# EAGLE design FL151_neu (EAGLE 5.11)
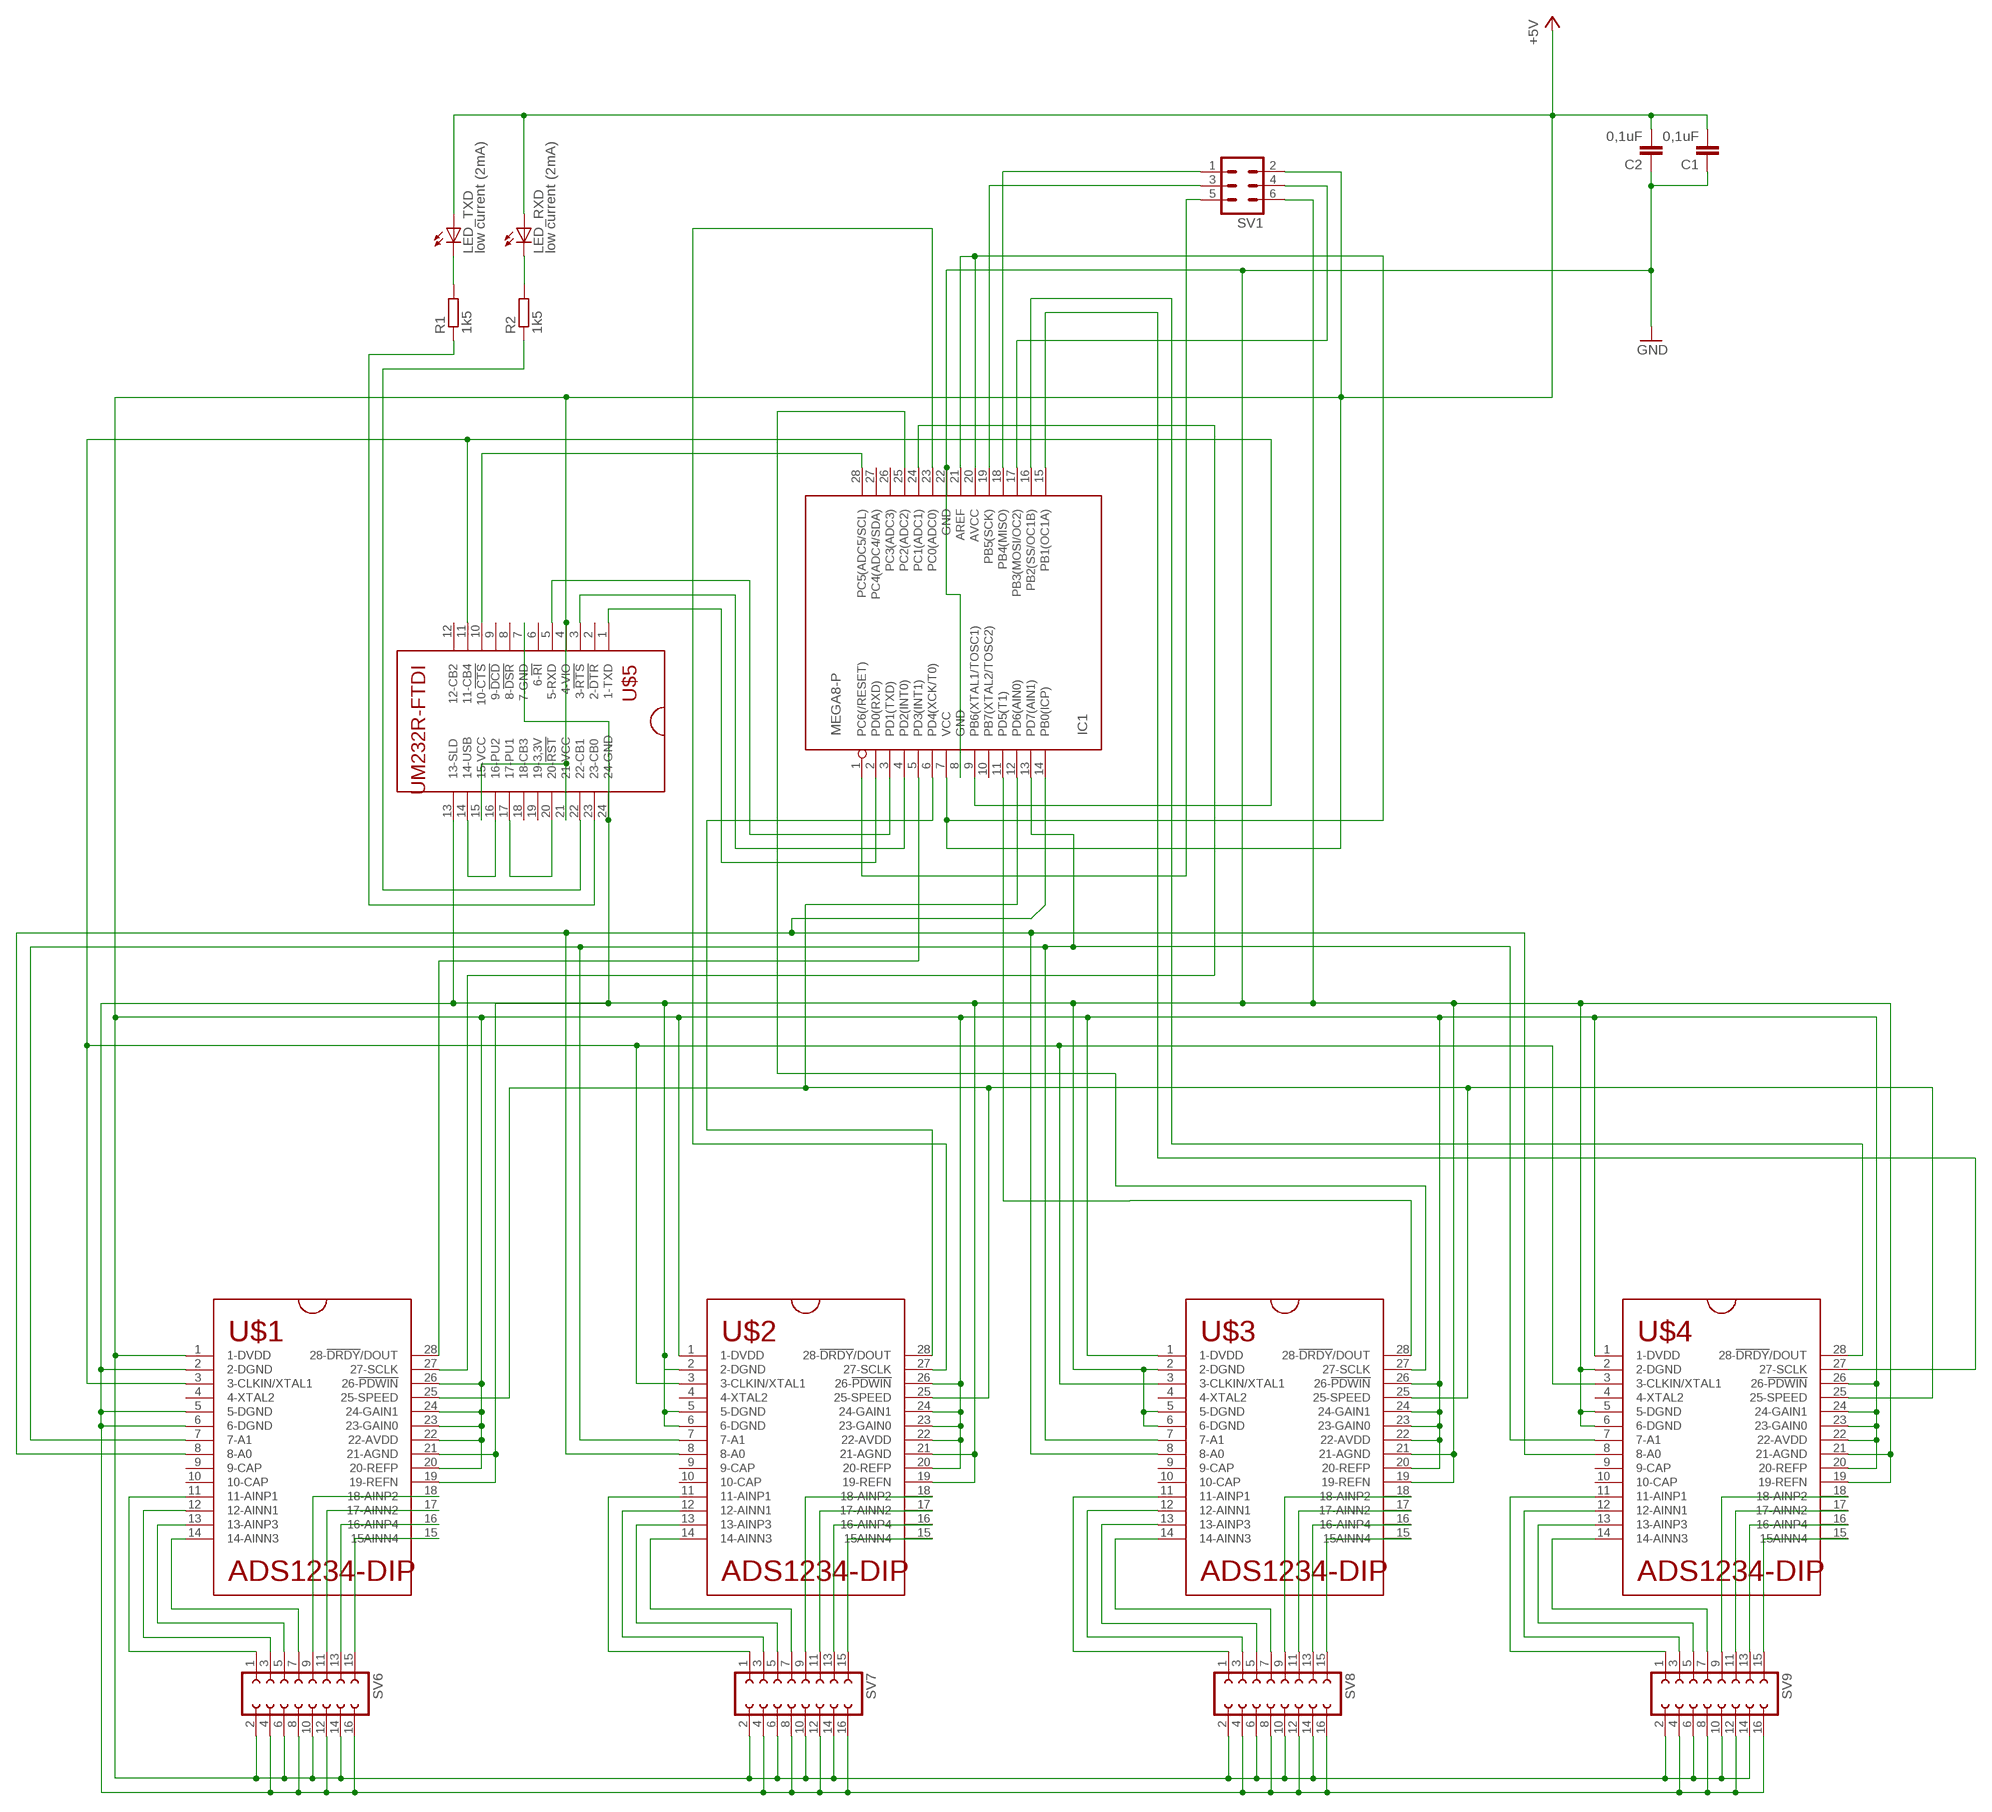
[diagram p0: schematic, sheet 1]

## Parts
C1  0,1uF  C-EU025-025X050  [C025-025X050]
C2  0,1uF  C-EU025-025X050  [C025-025X050]
IC1  MEGA8-P  [DIL28-3]
LED_RXD  low current (2mA)  LED3MM  [LED3MM]
LED_TXD  low current (2mA)  LED3MM  [LED3MM]
R1  1k5  R-EU_0207/10  [0207/10]
R2  1k5  R-EU_0207/10  [0207/10]
SV1  ML6  [ML6]
SV6  FE08-2  [FE08-2]
SV7  FE08-2  [FE08-2]
SV8  FE08-2  [FE08-2]
SV9  FE08-2  [FE08-2]
U$1  ADS1234-DIP  [ADS1234-DIP]
U$2  ADS1234-DIP  [ADS1234-DIP]
U$3  ADS1234-DIP  [ADS1234-DIP]
U$4  ADS1234-DIP  [ADS1234-DIP]
U$5  UM232R-FTDI  [UM232R-FTDI]

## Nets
+5V: C1.2 C2.2 IC1.7(VCC) IC1.20(AVCC) IC1.21(AREF) LED_RXD.A LED_TXD.A SV1.2 SV6.2 SV6.6 SV6.10 SV6.14 SV7.2 SV7.6 SV7.10 SV7.14 SV8.2 SV8.6 SV8.10 SV8.14 SV9.2 SV9.6 SV9.10 SV9.14 U$1.1(1-DVDD) U$1.20(20-REFP) U$1.22(22-AVDD) U$1.23(23-GAIN0) U$1.24(24-GAIN1) U$1.26(26-!PDWIN) U$2.1(1-DVDD) U$2.20(20-REFP) U$2.22(22-AVDD) U$2.23(23-GAIN0) U$2.24(24-GAIN1) U$2.26(26-!PDWIN) U$3.1(1-DVDD) U$3.20(20-REFP) U$3.22(22-AVDD) U$3.23(23-GAIN0) U$3.24(24-GAIN1) U$3.26(26-!PDWIN) U$4.1(1-DVDD) U$4.20(20-REFP) U$4.22(22-AVDD) U$4.23(23-GAIN0) U$4.24(24-GAIN1) U$4.26(26-!PDWIN) U$5.4(4-VIO) U$5.15(15-VCC) U$5.21(21-VCC)
GND: C1.1 C2.1 IC1.8(GND) IC1.22(GND) SV1.6 SV6.4 SV6.8 SV6.12 SV6.16 SV7.4 SV7.8 SV7.12 SV7.16 SV8.4 SV8.8 SV8.12 SV8.16 SV9.4 SV9.8 SV9.12 SV9.16 U$1.2(2-DGND) U$1.5(5-DGND) U$1.6(6-DGND) U$1.19(19-REFN) U$1.21(21-AGND) U$2.2(2-DGND) U$2.5(5-DGND) U$2.6(6-DGND) U$2.19(19-REFN) U$2.21(21-AGND) U$3.2(2-DGND) U$3.5(5-DGND) U$3.6(6-DGND) U$3.19(19-REFN) U$3.21(21-AGND) U$4.2(2-DGND) U$4.5(5-DGND) U$4.6(6-DGND) U$4.19(19-REFN) U$4.21(21-AGND) U$5.7(7-GND) U$5.13(13-SLD) U$5.24(24-GND)
ISP: IC1.1(PC6(/RESET)) SV1.5
N$1: LED_TXD.K(C) R1.2
N$2: LED_RXD.K(C) R2.2
N$3: IC1.2(PD0(RXD)) U$5.1(1-TXD)
N$4: IC1.4(PD2(INT0)) U$5.3(3-!RTS)
N$5: IC1.3(PD1(TXD)) U$5.5(5-RXD)
N$6: IC1.6(PD4(XCK/T0)) U$2.28(28-!DRDY!/DOUT)
N$7: U$5.14(14-USB) U$5.16(16-PU2)
N$8: U$5.17(17-PU1) U$5.20(20-!RST)
N$9: IC1.24(PC1(ADC1)) U$1.27(27-SCLK)
N$10: R2.1 U$5.22(22-CB1)
N$11: R1.1 U$5.23(23-CB0)
N$12: SV6.1 U$1.11(11-AINP1)
N$13: IC1.5(PD3(INT1)) U$1.28(28-!DRDY!/DOUT)
N$14: IC1.15(PB1(OC1A)) U$4.27(27-SCLK)
N$15: IC1.16(PB2(SS/OC1B)) U$4.28(28-!DRDY!/DOUT)
N$16: IC1.12(PD6(AIN0)) U$1.25(25-SPEED) U$2.25(25-SPEED) U$3.25(25-SPEED) U$4.25(25-SPEED)
N$17: IC1.13(PD7(AIN1)) U$1.7(7-A1) U$2.7(7-A1) U$3.7(7-A1) U$4.7(7-A1)
N$18: IC1.25(PC2(ADC2)) U$3.27(27-SCLK)
N$19: IC1.11(PD5(T1)) U$3.28(28-!DRDY!/DOUT)
N$20: IC1.23(PC0(ADC0)) U$2.27(27-SCLK)
N$22: IC1.14(PB0(ICP)) U$1.8(8-A0) U$2.8(8-A0) U$3.8(8-A0) U$4.8(8-A0)
N$23: IC1.9(PB6(XTAL1/TOSC1)) U$1.3(3-CLKIN/XTAL1) U$2.3(3-CLKIN/XTAL1) U$3.3(3-CLKIN/XTAL1) U$4.3(3-CLKIN/XTAL1) U$5.11(11-CB4)
N$24: SV6.3 U$1.12(12-AINN1)
N$25: SV6.5 U$1.13(13-AINP3)
N$26: SV6.7 U$1.14(14-AINN3)
N$27: SV6.9 U$1.18(18-AINP2)
N$28: SV6.11 U$1.17(17-AINN2)
N$29: SV6.13 U$1.16(16-AINP4)
N$30: SV6.15 U$1.15(15AINN4)
N$31: SV7.1 U$2.11(11-AINP1)
N$32: SV7.3 U$2.12(12-AINN1)
N$33: SV7.5 U$2.13(13-AINP3)
N$34: SV7.7 U$2.14(14-AINN3)
N$35: SV7.9 U$2.18(18-AINP2)
N$36: SV7.11 U$2.17(17-AINN2)
N$37: SV7.13 U$2.16(16-AINP4)
N$38: SV7.15 U$2.15(15AINN4)
N$39: SV8.1 U$3.11(11-AINP1)
N$40: SV8.3 U$3.12(12-AINN1)
N$41: SV8.5 U$3.13(13-AINP3)
N$42: SV8.7 U$3.14(14-AINN3)
N$43: SV8.9 U$3.18(18-AINP2)
N$44: SV8.11 U$3.17(17-AINN2)
N$45: SV8.13 U$3.16(16-AINP4)
N$46: SV8.15 U$3.15(15AINN4)
N$47: SV9.1 U$4.11(11-AINP1)
N$48: SV9.3 U$4.12(12-AINN1)
N$49: SV9.5 U$4.13(13-AINP3)
N$50: SV9.7 U$4.14(14-AINN3)
N$51: SV9.9 U$4.18(18-AINP2)
N$52: SV9.11 U$4.17(17-AINN2)
N$53: SV9.13 U$4.16(16-AINP4)
N$54: SV9.15 U$4.15(15AINN4)
N$55: IC1.19(PB5(SCK)) SV1.3
N$56: IC1.17(PB3(MOSI/OC2)) SV1.4
N$57: IC1.18(PB4(MISO)) SV1.1
N$58: IC1.28(PC5(ADC5/SCL)) U$5.10(10-!CTS)
Unconnected: IC1.10(PB7(XTAL2/TOSC2)) IC1.26(PC3(ADC3)) IC1.27(PC4(ADC4/SDA)) U$1.4(4-XTAL2) U$1.9(9-CAP) U$1.10(10-CAP) U$2.4(4-XTAL2) U$2.9(9-CAP) U$2.10(10-CAP) U$3.4(4-XTAL2) U$3.9(9-CAP) U$3.10(10-CAP) U$4.4(4-XTAL2) U$4.9(9-CAP) U$4.10(10-CAP) U$5.2(2-!DTR) U$5.6(6-!RI) U$5.8(8-!DSR) U$5.9(9-!DCD) U$5.12(12-CB2) U$5.18(18-CB3) U$5.19(19-3,3V)

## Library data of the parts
C1 C2 = rcl:C-EU: CAPACITOR, European symbol
IC1 = balzes_bauteile:MEGA8-P: MICROCONTROLLER 8 Kbytes FLASH, 1 kbytes SRAM, 512 bytes EEPROM, USART, 4-channel 10 bit ADC, 2-channel 8 bit ADC Pin compatible with Atmega48, ATMega88, ATMega168 Source: avr.lbr
LED_RXD LED_TXD = led:LED: LED
R1 R2 = rcl:R-EU_: RESISTOR, European symbol
SV1 = con-harting-ml:ML6: HARTING
SV6-SV9 = con-lsta:FE08-2: FEMALE HEADER
U$1-U$4 = balzes_bauteile:ADS1234-DIP: Texas Instruments ADS1234 auf break-out-board DIP28,6 4 Kanal 24-bit Analog-Digital-Converter für Messbrücken
U$5 = balzes_bauteile:UM232R-FTDI

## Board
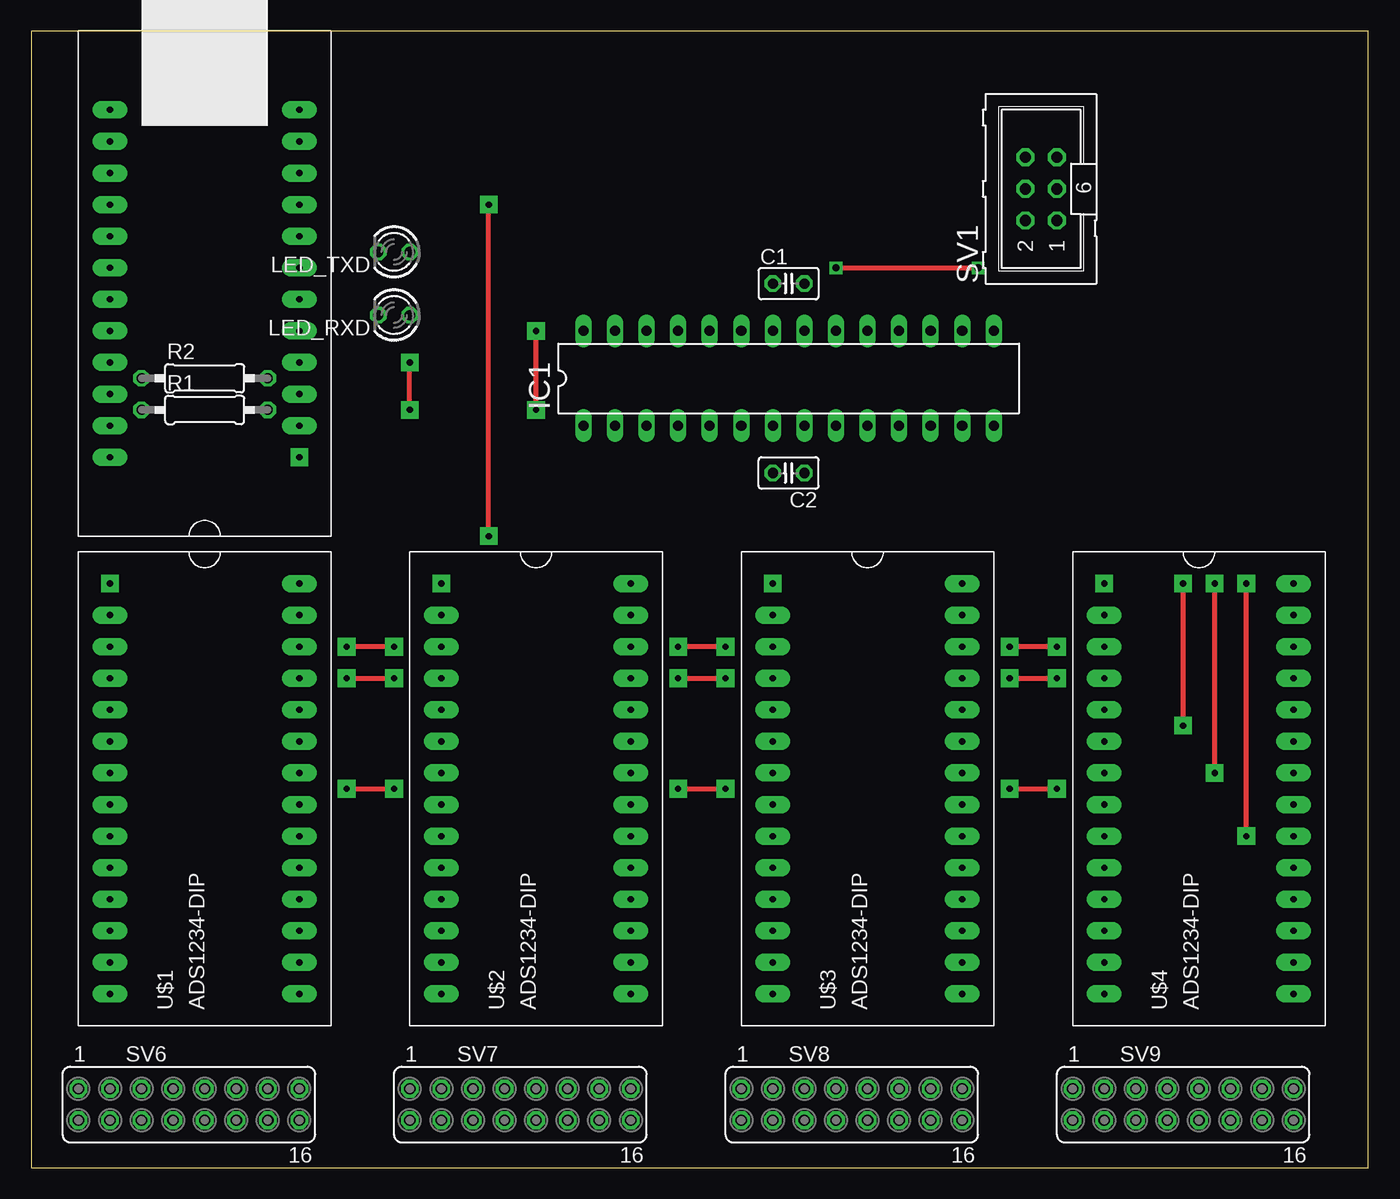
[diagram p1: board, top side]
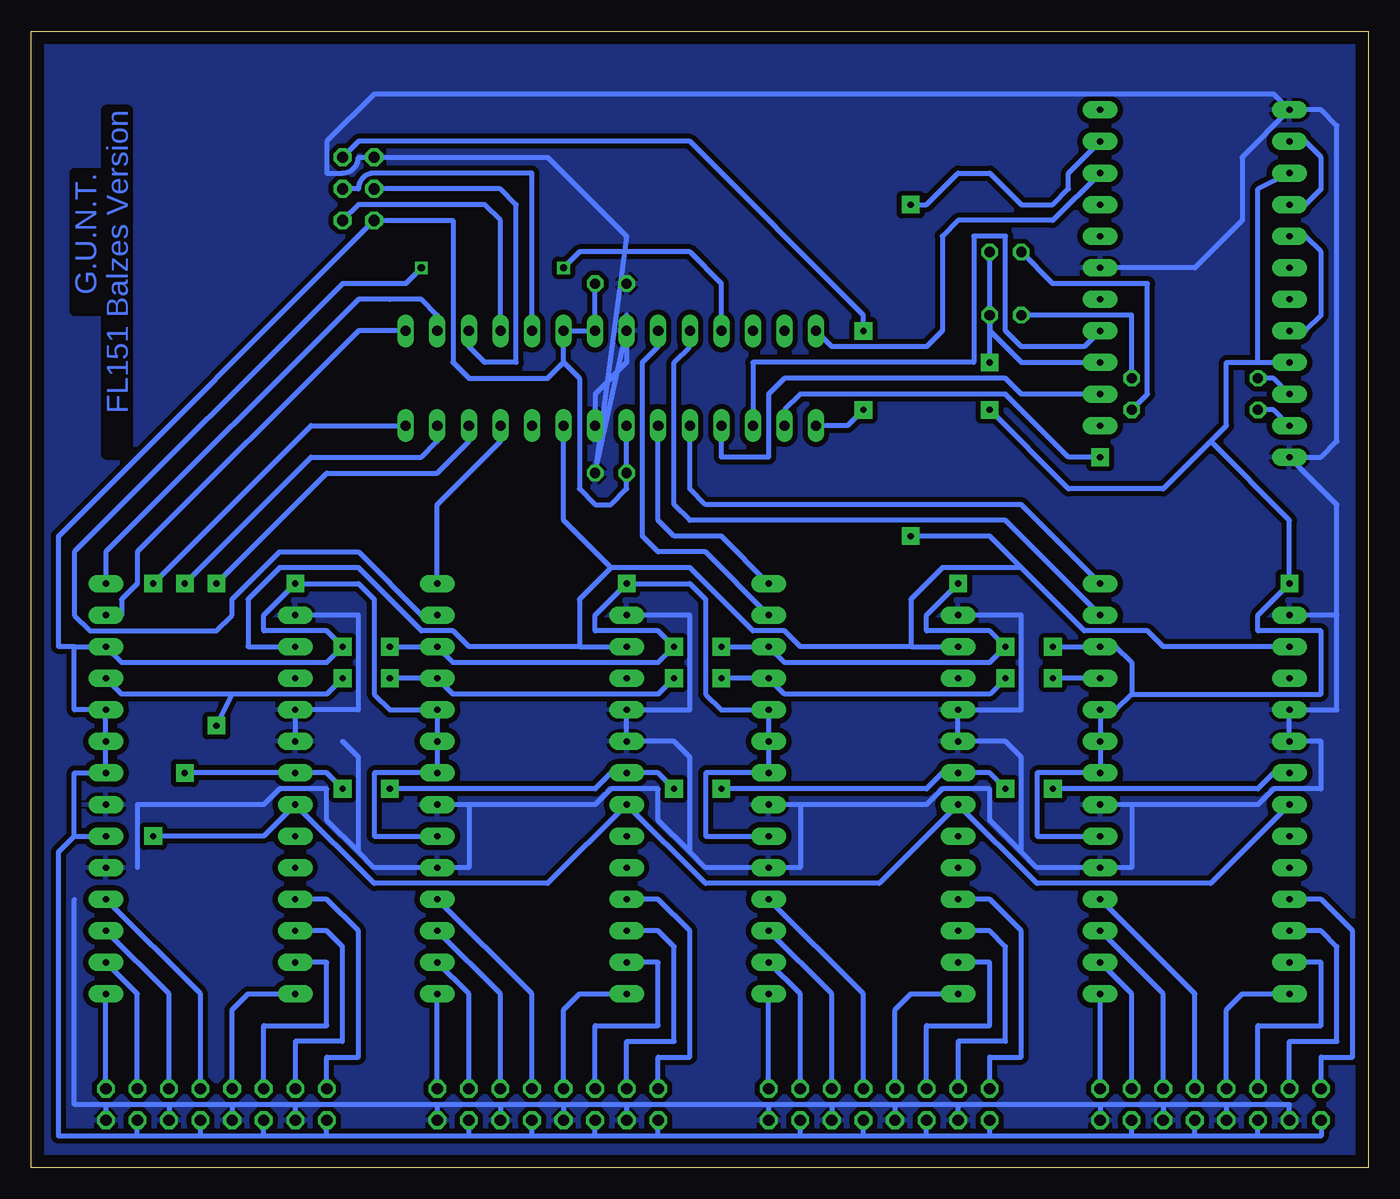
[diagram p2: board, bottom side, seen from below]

Size 107.62 x 91.43 mm. Coordinates in mm from the lower left corner, seen from the top.
Outline: 0,0 107.62,0 107.62,91.43 0,91.43 0,0
Copper layers (1*16): Top 0.035mm / dielectric 1.5mm / Bottom 0.035mm
Design rules "default": minimum track width 10mil, minimum drill 24mil, track to track 8mil, track to pad 8mil, pad to pad 8mil, via to via 8mil, smd to smd 8mil, copper to edge 40mil, drill to drill 8mil, minimum pad ring 10mil, minimum via ring 8mil, stop-mask expansion 4mil, vias tented up to drill 0mil, thermal gap 10mil

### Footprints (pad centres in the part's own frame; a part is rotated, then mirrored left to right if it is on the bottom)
C025-025X050 = drill 0.813 octagon: 1 -1.27,0; 2 1.27,0
DIL28-3 = drill 0.813 long: 1 -16.51,-3.81; 2 -13.97,-3.81; 3 -11.43,-3.81; 4 -8.89,-3.81; 5 -6.35,-3.81; 6 -3.81,-3.81; 7 -1.27,-3.81; 8 1.27,-3.81; 9 3.81,-3.81; 10 6.35,-3.81; 11 8.89,-3.81; 12 11.43,-3.81; 13 13.97,-3.81; 14 16.51,-3.81; 15 16.51,3.81; 16 13.97,3.81; 17 11.43,3.81; 18 8.89,3.81; 19 6.35,3.81; 20 3.81,3.81; 21 1.27,3.81; 22 -1.27,3.81; 23 -3.81,3.81; 24 -6.35,3.81; 25 -8.89,3.81; 26 -11.43,3.81; 27 -13.97,3.81; 28 -16.51,3.81
LED3MM = drill 0.813 octagon: A -1.27,0; K 1.27,0
0207/10 = drill 0.813 octagon: 1 -5.08,0; 2 5.08,0
ML6 = drill 0.914 octagon: 1 -2.54,-1.27; 2 -2.54,1.27; 3 0,-1.27; 4 0,1.27; 5 2.54,-1.27; 6 2.54,1.27
FE08-2 = drill 0.914 octagon: 1 -8.89,1.27; 2 -8.89,-1.27; 3 -6.35,1.27; 4 -6.35,-1.27; 5 -3.81,1.27; 6 -3.81,-1.27; 7 -1.27,1.27; 8 -1.27,-1.27; 9 1.27,1.27; 10 1.27,-1.27; 11 3.81,1.27; 12 3.81,-1.27; 13 6.35,1.27; 14 6.35,-1.27; 15 8.89,1.27; 16 8.89,-1.27
ADS1234-DIP = drill 0.5 pad 1.422 square: 1 -7.62,16.51 | drill 0.5 pad 1.422 long: 2 -7.62,13.97; 3 -7.62,11.43; 4 -7.62,8.89; 5 -7.62,6.35; 6 -7.62,3.81; 7 -7.62,1.27; 8 -7.62,-1.27; 9 -7.62,-3.81; 10 -7.62,-6.35; 11 -7.62,-8.89; 12 -7.62,-11.43; 13 -7.62,-13.97; 14 -7.62,-16.51; 15 7.62,-16.51; 16 7.62,-13.97; 17 7.62,-11.43; 18 7.62,-8.89; 19 7.62,-6.35; 20 7.62,-3.81; 21 7.62,-1.27; 22 7.62,1.27; 23 7.62,3.81; 24 7.62,6.35; 25 7.62,8.89; 26 7.62,11.43; 27 7.62,13.97; 28 7.62,16.51
UM232R-FTDI = drill 0.5 pad 1.422 square: 1 -16.51,30.48 | drill 0.5 pad 1.422 long: 2 -16.51,27.94; 3 -16.51,25.4; 4 -16.51,22.86; 5 -16.51,20.32; 6 -16.51,17.78; 7 -16.51,15.24; 8 -16.51,12.7; 9 -16.51,10.16; 10 -16.51,7.62; 11 -16.51,5.08; 12 -16.51,2.54; 13 -1.27,2.54; 14 -1.27,5.08; 15 -1.27,7.62; 16 -1.27,10.16; 17 -1.27,12.7; 18 -1.27,15.24; 19 -1.27,17.78; 20 -1.27,20.32; 21 -1.27,22.86; 22 -1.27,25.4; 23 -1.27,27.94; 24 -1.27,30.48

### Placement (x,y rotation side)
C1  60.96,71.12 0 top
C2  60.96,55.88 180 top
IC1  60.96,63.5 0 top
LED_RXD  29.21,68.58 180 top
LED_TXD  29.21,73.66 180 top
R1  13.97,60.96 0 top
R2  13.97,63.5 0 top
SV1  81.28,78.74 90 top
SV6  12.7,5.08 0 top
SV7  39.37,5.08 0 top
SV8  66.04,5.08 0 top
SV9  92.71,5.08 0 top
U$1  13.97,30.48 0 top
U$2  40.64,30.48 0 top
U$3  67.31,30.48 0 top
U$4  93.98,30.48 0 top
U$5  5.08,87.63 180 top

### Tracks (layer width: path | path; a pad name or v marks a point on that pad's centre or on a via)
+5V  (via drill 0.5 pad 1.42)
  Top 0.406: v29.21,41.91 v25.4,41.91 | v55.88,41.91 v52.07,41.91 | v82.55,41.91 v78.74,41.91 | v30.48,60.96 v30.48,64.77
  Bottom 0.406: 19.05,38.1 20.32,36.83 U$1.24 U$1.23 U$1.22 26.67,31.75 26.67,26.67 U$1.20 | 19.05,38.1 19.05,40.64 20.32,41.91 U$1.26 v25.4,41.91 | 19.05,38.1 3.81,38.1 3.81,43.18 8.89,43.18 8.89,44.45 U$1.1 6.35,52.07 12.7,58.42 | U$2.20 53.34,26.67 53.34,31.75 U$2.22 U$2.23 U$2.24 52.07,36.83 53.34,38.1 53.34,45.72 54.61,46.99 U$3.1 62.23,44.45 62.23,43.18 57.15,43.18 v55.88,41.91 57.15,40.64 73.66,40.64 U$3.26 v78.74,41.91 | U$2.1 35.56,44.45 35.56,43.18 30.48,43.18 v29.21,41.91 30.48,40.64 46.99,40.64 U$2.26 v52.07,41.91 | U$3.20 80.01,26.67 80.01,31.75 U$3.22 U$3.23 U$3.24 78.74,36.83 80.01,38.1 80.01,45.72 81.28,46.99 U$4.1 88.9,44.45 88.9,43.18 83.82,43.18 v82.55,41.91 83.82,40.64 100.33,40.64 U$4.26 104.14,41.91 | 104.14,41.91 104.14,36.83 U$4.24 U$4.23 U$4.22 104.14,31.75 104.14,26.67 | 104.14,41.91 105.41,41.91 105.41,50.8 SV1.2 73.66,76.2 73.66,64.77 72.39,63.5 66.04,63.5 64.77,64.77 | 104.14,26.67 U$4.20 | 99.06,2.54 105.41,2.54 105.41,25.4 104.14,26.67 | 99.06,2.54 SV9.14 | 93.98,2.54 99.06,2.54 | 93.98,2.54 SV9.10 | 88.9,2.54 93.98,2.54 | 88.9,2.54 SV9.6 | 83.82,2.54 88.9,2.54 | 83.82,2.54 SV9.2 | 72.39,2.54 83.82,2.54 | 72.39,2.54 SV8.14 | 67.31,2.54 72.39,2.54 | 67.31,2.54 SV8.10 | 62.23,2.54 67.31,2.54 | 62.23,2.54 SV8.6 | 57.15,2.54 62.23,2.54 | 57.15,2.54 SV8.2 | 45.72,2.54 57.15,2.54 | 45.72,2.54 SV7.14 | 40.64,2.54 45.72,2.54 | 40.64,2.54 SV7.10 | 35.56,2.54 40.64,2.54 | 35.56,2.54 SV7.6 | 30.48,2.54 35.56,2.54 | 30.48,2.54 SV7.2 | 19.05,2.54 30.48,2.54 | 19.05,2.54 SV6.14 | 13.97,2.54 19.05,2.54 | 13.97,2.54 SV6.10 | 8.89,2.54 13.97,2.54 | 8.89,2.54 SV6.6 | 8.89,2.54 3.81,2.54 SV6.2 | 12.7,58.42 11.43,59.69 11.43,64.77 8.89,64.77
  Bottom 0.406: 8.89,64.77 U$5.21 | U$5.15 8.89,78.74 8.89,64.77 | U$5.4 27.94,64.77 30.48,67.31 LED_RXD.A | LED_RXD.A LED_TXD.A | 64.77,64.77 IC1.20 IC1.21 C1.2 | 64.77,64.77 63.5,63.5 63.5,54.61 62.23,53.34 60.96,53.34 59.69,54.61 C2.2 IC1.7 | v30.48,64.77 LED_RXD.A | v30.48,60.96 24.13,54.61 16.51,54.61 12.7,58.42
GND
  Bottom 0.406: 19.05,29.21 19.05,24.13 U$1.19 26.67,24.13 27.94,25.4 | 27.94,25.4 27.94,33.02 29.21,34.29 U$2.6 U$2.5 27.94,36.83 27.94,44.45 U$2.2 | 2.54,44.45 U$1.2 | 2.54,44.45 2.54,36.83 U$1.5 U$1.6 3.81,34.29 3.81,30.48 7.62,30.48 8.89,29.21 19.05,29.21 | 27.94,25.4 30.48,27.94 30.48,30.48 34.29,30.48 35.56,29.21 45.72,29.21 | 45.72,29.21 U$2.21 | 45.72,29.21 45.72,24.13 U$2.19 53.34,24.13 54.61,25.4 | 19.05,29.21 U$1.21 | 54.61,25.4 57.15,27.94 57.15,30.48 60.96,30.48 62.23,29.21 72.39,29.21 | 72.39,29.21 U$3.21 | 72.39,29.21 72.39,24.13 U$3.19 80.01,24.13 81.28,25.4 | 54.61,25.4 54.61,33.02 55.88,34.29 U$3.6 U$3.5 54.61,36.83 54.61,44.45 U$3.2 | 81.28,25.4 83.82,27.94 83.82,30.48 87.63,30.48 88.9,29.21 99.06,29.21 99.06,24.13 | 81.28,25.4 81.28,33.02 82.55,34.29 | 104.14,21.59 104.14,5.08 101.6,5.08 | 101.6,5.08 SV9.16 | 96.52,5.08 SV9.12 | 96.52,5.08 101.6,5.08 | 91.44,5.08 SV9.8 | 91.44,5.08 96.52,5.08 | 86.36,5.08 SV9.4 | 86.36,5.08 91.44,5.08 | 74.93,5.08 SV8.16 | 74.93,5.08 86.36,5.08 | 69.85,5.08 74.93,5.08 | 69.85,5.08 SV8.12 | 64.77,5.08 69.85,5.08 | 64.77,5.08 SV8.8 | 59.69,5.08 64.77,5.08 | 59.69,5.08 SV8.4 | 48.26,5.08 59.69,5.08 | 48.26,5.08 SV7.16 | 43.18,5.08 48.26,5.08 | 43.18,5.08 SV7.12 | 38.1,5.08 43.18,5.08 | 38.1,5.08 SV7.8 | 33.02,5.08 38.1,5.08 | 33.02,5.08 SV7.4 | 21.59,5.08 33.02,5.08 | 21.59,5.08 SV6.16 | 16.51,5.08 21.59,5.08 | 16.51,5.08 SV6.12 | 11.43,5.08 16.51,5.08 | 11.43,5.08 SV6.8 | 11.43,5.08 6.35,5.08 SV6.4 | U$5.13 3.81,85.09 2.54,83.82 2.54,58.42 3.81,57.15 U$5.24 2.54,53.34 2.54,44.45 | U$5.13 7.62,86.36 80.01,86.36 83.82,82.55 83.82,80.01 82.55,80.01 arc-90 81.28,81.28 SV1.6 66.04,81.28 59.69,74.93 C2.1 IC1.22
  Bottom 0.406: U$5.7 13.97,72.39 10.16,76.2 10.16,81.28 U$5.13 | IC1.22 59.69,64.77 62.23,62.23 IC1.8 | IC1.22 59.69,68.58 | U$4.6 U$4.5 81.28,36.83 81.28,44.45 U$4.2
  pour Bottom (isolate 0.406): 0,91.44 107.95,91.44 107.95,0 0,0
ISP  (via drill 0.5 pad 1.42)
  Top 0.406: v40.64,60.96 v40.64,67.31
  Bottom 0.406: IC1.1 41.91,59.69 v40.64,60.96 | v40.64,67.31 40.64,68.58 54.61,82.55 81.28,82.55 SV1.5
N$1
  Bottom 0.406: R1.2 17.78,62.23 17.78,71.12 25.4,71.12 LED_TXD.K
N$2
  Bottom 0.406: R2.2 19.05,68.58 LED_RXD.K
N$3
  Bottom 0.406: U$5.1 24.13,57.15 29.21,62.23 45.72,62.23 46.99,60.96 IC1.2
N$4
  Bottom 0.406: U$5.3 27.94,62.23 29.21,63.5 46.99,63.5 48.26,62.23 48.26,57.15 52.07,57.15 IC1.4
N$5
  Bottom 0.406: U$5.5 22.86,66.04 27.94,66.04 29.21,67.31 29.21,74.93 31.75,74.93 31.75,64.77 49.53,64.77 IC1.3
N$6
  Bottom 0.406: U$2.28 52.07,50.8 55.88,50.8 57.15,52.07 IC1.6
N$7
  Bottom 0.406: U$5.14 5.08,82.55 3.81,81.28 3.81,78.74 5.08,77.47 U$5.16
N$8
  Bottom 0.406: U$5.20 5.08,67.31 3.81,68.58 3.81,73.66 5.08,74.93 U$5.17
N$9
  Bottom 0.406: U$1.27 29.21,52.07 54.61,52.07 55.88,53.34 55.88,64.77 54.61,66.04 IC1.24
N$10
  Bottom 0.406: U$5.22 7.62,63.5 R2.1
N$11
  Bottom 0.406: U$5.23 7.62,60.96 R1.1
N$12
  Bottom 0.406: SV6.1 3.81,8.89 1.27,8.89 1.27,19.05 3.81,21.59 U$1.11
N$13
  Bottom 0.406: U$1.28 27.94,53.34 53.34,53.34 54.61,54.61 IC1.5
N$14
  Bottom 0.406: IC1.15 81.28,67.31 99.06,49.53 99.06,46.99 100.33,45.72 100.33,44.45 U$4.27
N$15
  Bottom 0.406: IC1.16 74.93,68.58 76.2,69.85 78.74,69.85 81.28,69.85 101.6,49.53 U$4.28
N$16  (via drill 0.5 pad 1.42)
  Top 0.406: v25.4,39.37 v29.21,39.37 | v52.07,39.37 v55.88,39.37 | v78.74,39.37 v82.55,39.37 | v92.71,35.56 v92.71,46.99
  Bottom 0.406: U$1.25 v25.4,39.37 | v29.21,39.37 30.48,38.1 46.99,38.1 U$2.25 v52.07,39.37 | v55.88,39.37 57.15,38.1 73.66,38.1 U$3.25 v78.74,39.37 | v82.55,39.37 83.82,38.1 91.44,38.1 | 91.44,38.1 100.33,38.1 U$4.25 | IC1.12 72.39,58.42 74.93,55.88 83.82,55.88 v92.71,46.99 | 91.44,38.1 v92.71,35.56
N$17  (via drill 0.5 pad 1.42)
  Top 0.406: v25.4,30.48 v29.21,30.48 | v52.07,30.48 v55.88,30.48 | v78.74,30.48 v82.55,30.48 | v95.25,31.75 v95.25,46.99
  Bottom 0.406: U$1.7 7.62,31.75 8.89,30.48 v25.4,30.48 | v29.21,30.48 30.48,31.75 U$2.7 34.29,31.75 35.56,30.48 v52.07,30.48 | v55.88,30.48 57.15,31.75 U$3.7 60.96,31.75 62.23,30.48 v78.74,30.48 | v82.55,30.48 83.82,31.75 U$4.7 v95.25,31.75 | IC1.13 74.93,58.42 76.2,57.15 85.09,57.15 v95.25,46.99
N$18  (via drill 0.6)
  Top 0.406: v64.77,72.39 v76.2,72.39
  Bottom 0.406: U$3.27 76.2,44.45 81.28,49.53 87.63,49.53 91.44,45.72 91.44,44.45 92.71,43.18 102.87,43.18 104.14,44.45 104.14,49.53 82.55,71.12 77.47,71.12 v76.2,72.39 | v64.77,72.39 63.5,73.66 54.61,73.66 52.07,71.12 IC1.25
N$19
  Bottom 0.406: IC1.11 69.85,58.42 74.93,53.34 U$3.28
N$20
  Bottom 0.406: IC1.23 57.15,66.04 58.42,64.77 58.42,50.8 57.15,49.53 53.34,49.53 U$2.27
N$22  (via drill 0.5 pad 1.42)
  Top 0.406: v97.79,26.67 v97.79,46.99
  Bottom 0.406: U$1.8 12.7,22.86 26.67,22.86 U$2.8 39.37,22.86 53.34,22.86 U$3.8 66.04,22.86 80.01,22.86 U$4.8 88.9,26.67 v97.79,26.67 | IC1.14 85.09,59.69 v97.79,46.99
N$23  (via drill 0.5 pad 1.42)
  Top 0.406: v36.83,50.8 v36.83,77.47
  Bottom 0.406: U$1.3 16.51,41.91 17.78,43.18 22.86,43.18 27.94,48.26 | 27.94,48.26 34.29,48.26 36.83,45.72 36.83,41.91 | 36.83,41.91 U$2.3 | 36.83,41.91 45.72,41.91 46.99,43.18 49.53,43.18 54.61,48.26 60.96,48.26 | 60.96,48.26 63.5,45.72 63.5,41.91 | 63.5,41.91 U$3.3 | 63.5,41.91 72.39,41.91 73.66,43.18 76.2,43.18 81.28,48.26 87.63,48.26 90.17,45.72 90.17,41.91 U$4.3 | IC1.9 64.77,52.07 60.96,48.26 | 27.94,48.26 30.48,50.8 v36.83,50.8 | v36.83,77.47 35.56,77.47 33.02,80.01 30.48,80.01 27.94,77.47 25.4,77.47 24.13,78.74 24.13,80.01 U$5.11
N$24
  Bottom 0.406: SV6.3 6.35,10.16 2.54,10.16 2.54,17.78 3.81,19.05 U$1.12
N$25
  Bottom 0.406: SV6.5 8.89,11.43 3.81,11.43 3.81,16.51 U$1.13
N$26
  Bottom 0.406: SV6.7 11.43,12.7 10.16,13.97 U$1.14
N$27
  Bottom 0.406: SV6.9 13.97,13.97 U$1.18
N$28
  Bottom 0.406: SV6.11 16.51,13.97 U$1.17
N$29
  Bottom 0.406: U$1.16 19.05,13.97 SV6.13
N$30
  Bottom 0.406: SV6.15 U$1.15
N$31
  Bottom 0.406: SV7.1 30.48,8.89 27.94,8.89 27.94,19.05 30.48,21.59 U$2.11
N$32
  Bottom 0.406: SV7.3 33.02,10.16 29.21,10.16 29.21,17.78 30.48,19.05 U$2.12
N$33
  Bottom 0.406: SV7.5 35.56,11.43 30.48,11.43 30.48,13.97 30.48,16.51 U$2.13
N$34
  Bottom 0.406: U$2.14 36.83,13.97 38.1,12.7 SV7.7
N$35
  Bottom 0.406: U$2.18 40.64,13.97 SV7.9
N$36
  Bottom 0.406: U$2.17 43.18,13.97 SV7.11
N$37
  Bottom 0.406: U$2.16 45.72,13.97 SV7.13
N$38
  Bottom 0.406: SV7.15 U$2.15
N$39
  Bottom 0.406: U$3.11 57.15,21.59 54.61,19.05 54.61,8.89 57.15,8.89 SV8.1
N$40
  Bottom 0.406: U$3.12 57.15,19.05 55.88,17.78 55.88,10.16 59.69,10.16 SV8.3
N$41
  Bottom 0.406: U$3.13 57.15,16.51 57.15,11.43 62.23,11.43 SV8.5
N$42
  Bottom 0.406: SV8.7 64.77,12.7 63.5,13.97 U$3.14
N$43
  Bottom 0.406: U$3.18 67.31,13.97 SV8.9
N$44
  Bottom 0.406: U$3.17 69.85,13.97 SV8.11
N$45
  Bottom 0.406: U$3.16 72.39,13.97 SV8.13
N$46
  Bottom 0.406: SV8.15 U$3.15
N$47
  Bottom 0.406: SV9.1 83.82,8.89 81.28,8.89 81.28,19.05 83.82,21.59 U$4.11
N$48
  Bottom 0.406: U$4.12 83.82,19.05 82.55,17.78 82.55,10.16 86.36,10.16 SV9.3
N$49
  Bottom 0.406: U$4.13 83.82,16.51 83.82,11.43 88.9,11.43 SV9.5
N$50
  Bottom 0.406: SV9.7 91.44,12.7 90.17,13.97 U$4.14
N$51
  Bottom 0.406: U$4.18 93.98,13.97 SV9.9
N$52
  Bottom 0.406: U$4.17 96.52,13.97 SV9.11
N$53
  Bottom 0.406: U$4.16 99.06,13.97 SV9.13
N$54
  Bottom 0.406: SV9.15 U$4.15
N$55
  Bottom 0.406: SV1.3 81.28,78.74 arc90 80.01,80.01 67.31,80.01 IC1.19
N$56
  Bottom 0.406: IC1.17 72.39,66.04 71.12,64.77 68.58,64.77 68.58,77.47 69.85,78.74 SV1.4
N$57
  Bottom 0.406: IC1.18 69.85,76.2 71.12,77.47 81.28,77.47 SV1.1
N$58
  Bottom 0.406: U$5.10 25.4,76.2 33.02,76.2 34.29,74.93 34.29,67.31 35.56,66.04 43.18,66.04 IC1.28

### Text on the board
Bottom: FL151 Balzes Version | G.U.N.T.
